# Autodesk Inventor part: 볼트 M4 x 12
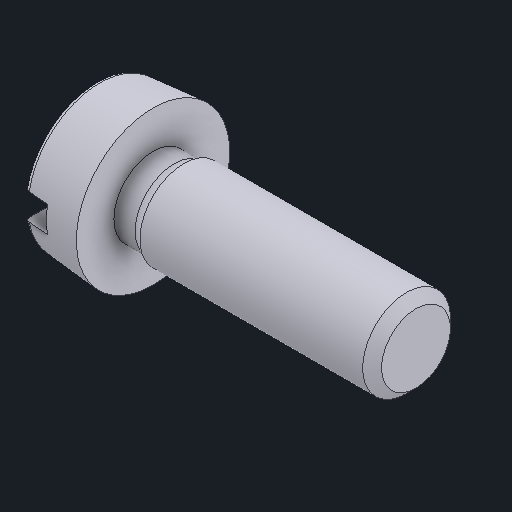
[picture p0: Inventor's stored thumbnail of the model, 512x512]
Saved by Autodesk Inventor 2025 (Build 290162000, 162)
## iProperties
Created: 2025-08
Part Number: 볼트 M4 x 12
Material: 강철, 연강
Description: 6각머리 태핑 나사
Document SubType Name: Modeling
Designer: infra027
Density: 7.85 g/cm^3
Appearance: 기본값
Author: jhkim
Sending System: Autodesk Inventor 2026
Preprocessor: ST-DEVELOPER v20.1
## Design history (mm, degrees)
feature "Solid1"
node "솔리드1"
